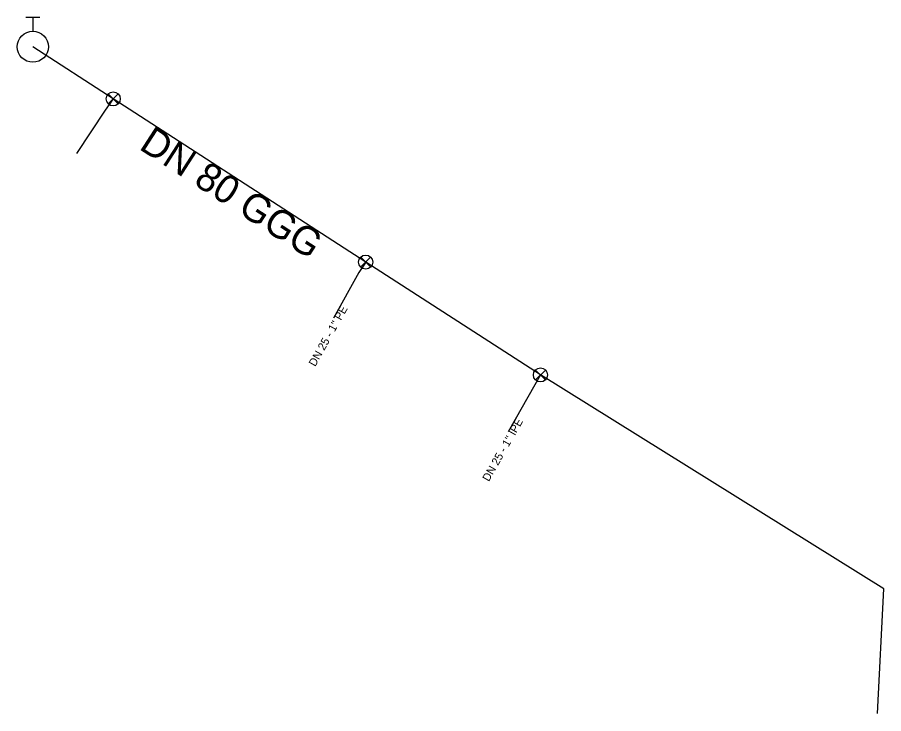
# Model space of a CAD drawing. Extents: x -492321 to -492053, y -1126159 to -1125902.
# Drawn here: x -492110.19 to -492060.92, y -1126159.44 to -1126119.84 of the extents above; entities that cross this region are included whole.
import ezdxf

# ---------------------------------------------------------------- set-up
doc = ezdxf.new("R2010")
doc.units = 0
for name, color, linetype in [('_pripojka_prevzato_z_dokumentace_', 7, 'Continuous'), ('_pripojka_priblizne_', 7, 'Continuous'), ('_voda_smvak_prevzato_z_dokumentace_', 7, 'Continuous'), ('Default', 7, 'Continuous'), ('MoLevel 28', 7, 'Continuous'), ('MoLevel 32', 7, 'Continuous'), ('MoLevel 46', 7, 'Continuous'), ('MoLevel 53', 7, 'Continuous'), ('MoLevel 55', 7, 'Continuous')]:
    doc.layers.add(name, color=color, linetype=linetype)

# ---------------------------------------------------------------- blocks, each defined once
blk = doc.blocks.new('_uzaver_pripojka_')
at = {"layer": 'Default'}
for p, q in [((-0.000035, -0.000035), (0.000035, 0.000035)), ((0.000035, -0.000035), (-0.000035, 0.000035))]:
    blk.add_line(p, q, dxfattribs=at)
for radius in [0.00005, 0.0000025]:
    blk.add_circle((0, 0), radius, dxfattribs=at)
blk = doc.blocks.new('_hydrant_voda_')
at = {"layer": 'Default'}
for p, q in [((-0.0000225, 0.000095), (0.0000225, 0.000095)), ((0, 0.000095), (0, 0.00005))]:
    blk.add_line(p, q, dxfattribs=at)
blk.add_circle((0, 0), 0.00005, dxfattribs=at)

msp = doc.modelspace()

# ---------------------------------------------------------------- linework, layer by layer
at = {"layer": '_pripojka_prevzato_z_dokumentace_'}
for p, q in [((-492104.74, -1126124.48), (-492105.2, -1126125.12)), ((-492105.2, -1126125.12), (-492106.832, -1126127.596)), ((-492090.38, -1126133.76), (-492090.77, -1126134.36)), ((-492090.77, -1126134.36), (-492092.216, -1126136.95)), ((-492080.44, -1126140.18), (-492080.76, -1126140.74))]:
    msp.add_line(p, q, dxfattribs=at)
at = {"layer": '_pripojka_priblizne_'}
msp.add_line((-492080.76, -1126140.74), (-492082.281, -1126143.42), dxfattribs=at)
at = {"layer": '_voda_smvak_prevzato_z_dokumentace_'}
msp.add_lwpolyline([(-492061.269, -1126159.439), (-492060.92, -1126152.35), (-492080.44, -1126140.18), (-492090.38, -1126133.76), (-492104.74, -1126124.48), (-492109.31, -1126121.52)], dxfattribs=at)

# ---------------------------------------------------------------- block references
at = {"layer": 'MoLevel 28', "xscale": 17636.68430335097, "yscale": 17636.68430335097}
msp.add_blockref('_hydrant_voda_', (-492109.31, -1126121.52), dxfattribs=at)
at = {"layer": 'MoLevel 53', "xscale": 7999.999999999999, "yscale": 7999.999999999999}
for p in [(-492104.74, -1126124.48), (-492090.38, -1126133.76), (-492080.44, -1126140.18)]:
    msp.add_blockref('_uzaver_pripojka_', p, dxfattribs=at)

# ---------------------------------------------------------------- texts
at = {"layer": 'MoLevel 32'}
msp.add_text("DN 25 - 1'' IPE", height=0.455, rotation=60.4221, dxfattribs=at).set_placement((-492083.377, -1126146.273))
at = {"layer": 'MoLevel 46'}
msp.add_text('DN 80 GGG', height=1.6049, rotation=327.1279, dxfattribs=at).set_placement((-492103.332, -1126127.301))
at = {"layer": 'MoLevel 55'}
msp.add_text("DN 25 - 1'' PE", height=0.455, rotation=60.8253, dxfattribs=at).set_placement((-492093.25, -1126139.735))

doc.saveas('drawing.dxf')
